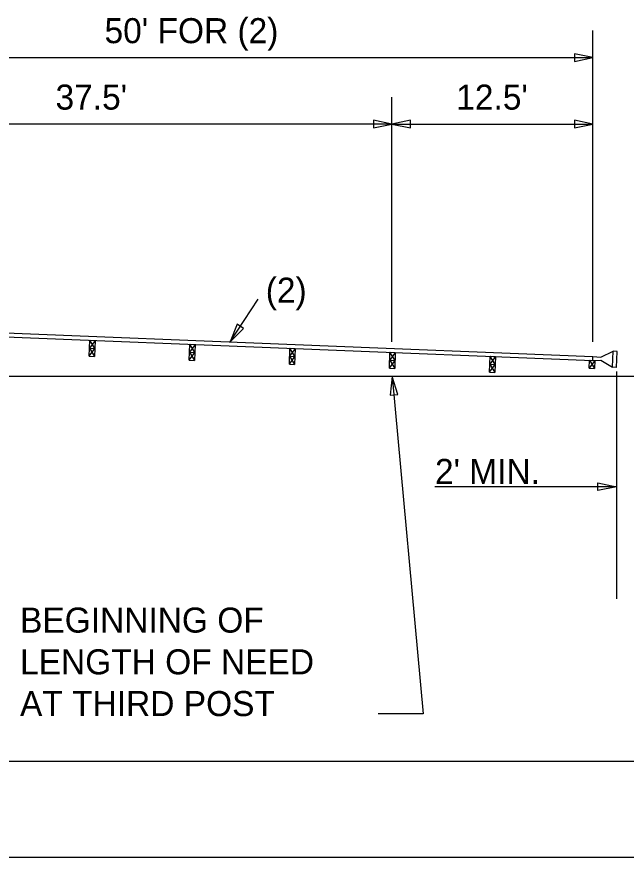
# Model space of a CAD drawing. Extents: x -439.1 to -407.9, y -458.1 to -436.2.
# Drawn here: x -417.05 to -413.4, y -445.9 to -440.87 of the extents above; entities that cross this region are included whole.
import ezdxf

# ---------------------------------------------------------------- set-up
doc = ezdxf.new("R2010")
doc.units = 0
doc.layers.add('Default', color=7, linetype='Continuous')

msp = doc.modelspace()

# ---------------------------------------------------------------- linework, layer by layer
at = {"layer": 'Default'}
for p, q in [((-413.6018, -442.8156), (-413.6018, -440.9524)), ((-418.4022, -441.1136), (-413.6018, -441.1136)), ((-414.8056, -442.8156), (-414.8056, -441.3503)), ((-414.8056, -441.5115), (-418.4022, -441.5115)), ((-414.8056, -441.5115), (-413.6018, -441.5115)), ((-422.599, -442.5673), (-413.603, -442.9273)), ((-422.598, -442.5433), (-413.602, -442.9033)), ((-415.7742, -442.8163), (-415.6067, -442.56)), ((-416.6192, -442.9027), (-416.6158, -442.8068)), ((-416.5839, -442.8079), (-416.6175, -442.8547)), ((-416.6158, -442.8068), (-416.5839, -442.8079)), ((-416.5855, -442.8559), (-416.6158, -442.8068)), ((-416.5998, -442.8073), (-416.5998, -442.8073)), ((-416.5839, -442.8079), (-416.5872, -442.9038)), ((-416.5839, -442.8079), (-416.5839, -442.8079)), ((-416.0197, -442.9267), (-416.0163, -442.8308)), ((-415.9843, -442.8319), (-416.018, -442.8787)), ((-416.0163, -442.8308), (-415.9843, -442.8319)), ((-415.986, -442.8798), (-416.0163, -442.8308)), ((-416.0003, -442.8313), (-416.0003, -442.8313)), ((-415.9843, -442.8319), (-415.9877, -442.9278)), ((-415.9843, -442.8319), (-415.9843, -442.8319)), ((-416.6192, -442.9027), (-416.5855, -442.8559)), ((-416.6175, -442.8547), (-416.5855, -442.8559)), ((-416.6175, -442.8547), (-416.5872, -442.9038)), ((-416.0197, -442.9267), (-415.986, -442.8798)), ((-416.018, -442.8787), (-415.986, -442.8798)), ((-416.018, -442.8787), (-415.9877, -442.9278)), ((-415.4201, -442.9507), (-415.4168, -442.8547)), ((-415.3848, -442.8559), (-415.4185, -442.9027)), ((-415.4168, -442.8547), (-415.3848, -442.8559)), ((-415.3865, -442.9038), (-415.4168, -442.8547)), ((-415.4008, -442.8553), (-415.4008, -442.8553)), ((-415.3848, -442.8559), (-415.3882, -442.9518)), ((-415.3848, -442.8559), (-415.3848, -442.8559)), ((-414.8206, -442.9746), (-414.8173, -442.8787)), ((-414.7853, -442.8798), (-414.8189, -442.9267)), ((-414.8173, -442.8787), (-414.7853, -442.8798)), ((-414.787, -442.9278), (-414.8173, -442.8787)), ((-414.8013, -442.8793), (-414.8013, -442.8793)), ((-414.7853, -442.8798), (-414.7886, -442.9758)), ((-414.7853, -442.8798), (-414.7853, -442.8798)), ((-413.554, -442.9083), (-413.481, -442.8723)), ((-413.485, -442.9683), (-413.481, -442.8723)), ((-413.457, -442.8733), (-413.481, -442.8723)), ((-413.461, -442.9693), (-413.457, -442.8733)), ((-416.6192, -442.9027), (-416.6192, -442.9027)), ((-416.6192, -442.9027), (-416.5872, -442.9038)), ((-416.0197, -442.9267), (-416.0197, -442.9267)), ((-416.0197, -442.9267), (-415.9877, -442.9278)), ((-415.4201, -442.9507), (-415.3865, -442.9038)), ((-415.4185, -442.9027), (-415.3865, -442.9038)), ((-415.4185, -442.9027), (-415.3882, -442.9518)), ((-414.8206, -442.9746), (-414.787, -442.9278)), ((-414.8189, -442.9267), (-414.787, -442.9278)), ((-414.8189, -442.9267), (-414.7886, -442.9758)), ((-414.2211, -442.9986), (-414.2177, -442.9027)), ((-414.1858, -442.9038), (-414.2194, -442.9507)), ((-414.2177, -442.9027), (-414.1858, -442.9038)), ((-414.1874, -442.9518), (-414.2177, -442.9027)), ((-414.2018, -442.9033), (-414.2018, -442.9033)), ((-414.1858, -442.9038), (-414.1891, -442.9997)), ((-414.1858, -442.9038), (-414.1858, -442.9038)), ((-413.625, -442.9743), (-413.623, -442.9263)), ((-413.591, -442.9273), (-413.625, -442.9743)), ((-413.623, -442.9263), (-413.591, -442.9273)), ((-413.623, -442.9263), (-413.593, -442.9753)), ((-413.603, -442.9273), (-413.602, -442.9033)), ((-413.603, -442.9273), (-413.555, -442.9263)), ((-413.602, -442.9033), (-413.554, -442.9083)), ((-413.591, -442.9273), (-413.593, -442.9753)), ((-413.555, -442.9263), (-413.485, -442.9683)), ((-415.4201, -442.9507), (-415.4201, -442.9507)), ((-415.4201, -442.9507), (-415.3882, -442.9518)), ((-414.8206, -442.9746), (-414.7886, -442.9758)), ((-414.8206, -442.9747), (-414.8206, -442.9747)), ((-414.2211, -442.9986), (-414.1874, -442.9518)), ((-414.2194, -442.9507), (-414.1874, -442.9518)), ((-414.2194, -442.9507), (-414.1891, -442.9997)), ((-413.625, -442.9743), (-413.593, -442.9753)), ((-413.461, -442.9693), (-413.485, -442.9683)), ((-413.348, -443.0233), (-434.25, -443.0233)), ((-414.8037, -443.0231), (-414.6188, -445.0437)), ((-414.2211, -442.9986), (-414.2211, -442.9986)), ((-414.2211, -442.9986), (-414.1891, -442.9997)), ((-413.461, -442.9949), (-413.461, -444.3555)), ((-413.461, -443.6847), (-414.5478, -443.6847)), ((-414.6188, -445.0437), (-414.888, -445.0437)), ((-437.226, -445.3273), (-410.372, -445.3273)), ((-437.226, -445.9033), (-410.372, -445.9033))]:
    msp.add_line(p, q, dxfattribs=at)
for points in [[(-413.7124, -441.1366), (-413.6018, -441.1136), (-413.7124, -441.0906)], [(-414.9163, -441.5344), (-414.8056, -441.5115), (-414.9163, -441.4885)], [(-414.695, -441.4885), (-414.8056, -441.5115), (-414.695, -441.5344)], [(-413.7124, -441.5344), (-413.6018, -441.5115), (-413.7124, -441.4885)], [(-415.7329, -442.7111), (-415.7742, -442.8163), (-415.6944, -442.7363)], [(-414.7708, -443.1312), (-414.8037, -443.0231), (-414.8165, -443.1354)], [(-413.5716, -443.6618), (-413.461, -443.6847), (-413.5716, -443.7077)]]:
    msp.add_lwpolyline(points, close=True, dxfattribs=at)

# ---------------------------------------------------------------- texts
for s, p in [("50' FOR (2)", (-416.527, -441.0274)), ("37.5'", (-416.8206, -441.4253)), ("12.5'", (-414.4204, -441.4253)), ('(2)', (-415.5614, -442.5817)), ("2' MIN.", (-414.5478, -443.6676)), ('BEGINNING OF', (-417.0331, -444.5581)), ('LENGTH OF NEED', (-417.0331, -444.8081)), ('AT THIRD POST', (-417.0331, -445.0581))]:
    msp.add_text(s, height=0.15, dxfattribs=at).set_placement(p)

doc.saveas('drawing.dxf')
